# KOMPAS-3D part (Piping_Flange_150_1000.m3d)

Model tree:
1. Plane XY
2. Plane ZX
3. Plane ZY
4. X Axis
5. Y Axis
6. Z Axis
7. Origin
8. Sketch:1
9. Extrude:1  (labels: На расстояние 1; На расстояние 2)
     Толщина стенки 1 = 1; Толщина стенки 2 = 1; Расстояние 2 = 10
10. Offset Plane:1
11. Sketch:2
12. Sketch:3
13. Offset Plane:2
14. Sketch:4
15. Loft:2  (labels: Толщина стенки 1; Толщина стенки 2)
16. Chamfer:2
     Угол = 26.5651
17. Sketch:7
18. Cut-Extrude:2  (labels: На расстояние 1)
     Толщина стенки 1 = 1; Толщина стенки 2 = 1; Расстояние 1 = 10; Расстояние 2 = 11
19. Intersection Axis of Two Planes:1
20. Circular Pattern:1  (labels: Экземпляр ( 1, 2 );; Вырезать элемент выдавливания:2; Экземпляр ( 1, 3 );; Вырезать элемент выдавливания:2)
21. Вырезать элемент выдавливания:2  (labels: Экземпляр ( 1, 6 );; Экземпляр ( 1, 7 );; Экземпляр ( 1, 8 );)
     N 1 = 1; Шаг 1 = 10; Шаг 2 = 360
22. Offset Plane:3
23. Sketch:8
24. Extrude:3  (labels: На расстояние 2)
     Толщина стенки 1 = 1; Толщина стенки 2 = 1; Расстояние 1 = 3; Угол 1 = 45; Расстояние 2 = 10
25. Sketch:6
26. Cut-Extrude:1  (labels: На расстояние 1; На расстояние 2)
     Толщина стенки 1 = 1; Толщина стенки 2 = 1; Расстояние 1 = 49; Расстояние 2 = 3
27. Sketch:9
28. Attachment Point:1
29. Sketch:10
30. Attachment Point:2  (labels: C:\Program Files\ASCON\KOMPAS-3D V10\Sys\graphic.lyt; Flange Dn 150; Piping_Flange_150_1000.m3d; Tank 2.a3d)

Expressions: (Dn-d1)*0.5-1; (Dm-Dn)*1.25; f*SIND(30)
Referenced files in C:\Documents and Settings\kashirsky\Мои документы\Camtasia Studio\Pipelines3D\Tanks\: Piping_Flange_150_1000.m3d, Tank 2.a3d, Tank 2.spw, Tank 1.a3d, Tank 1.spw, Tanks_step 1.a3d, Tanks_step 1.spw, Tanks_step 2.a3d, Tanks_step 3.a3d, Tanks_step 4.a3d
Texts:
  Flange Dn 150
  Steel ASTM A295
  Three Point Plane
  Plane at Angle
  Line and Point Plane
  Axis through Two Vertices
  Axis of Feature
  Axis of Conical Surface
  Axis through Edge
  Приклеить элемент выдавливания
  Приклеить элемент вращения
  Приклеить кинематический элемент
  Приклеить элемент по сечениям
  Trim by Surface
  Trim by Sketch
  Feature with No History
  Intersection Axis of Two Planes
  Two Line Plane
  Line and Face Plane
  Bend by line
  Hole in sheet body
  Cut in sheet body
  Point in CM
  Linear Dimension from Line to Point
  Surface Finish Symbol
  Geometric Tolerance Symbol
  Текст на чертеже
  Линия-выноска #1
  Линия-выноска #2
  Линия-выноска #3
  Отклонения формы и база
  Марка координационной оси
  Марка/позиционное обозначение с линией-выноской
  Марка/позиционное обозначение на линии
  Марка/позиционное обозначение без линии-выноски
  Экземпляр ( 1, 2 );
  Экземпляр ( 1, 3 );
  Экземпляр ( 1, 4 );
  Экземпляр ( 1, 5 );
  Экземпляр ( 1, 6 );
  Экземпляр ( 1, 7 );
  Экземпляр ( 1, 8 );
